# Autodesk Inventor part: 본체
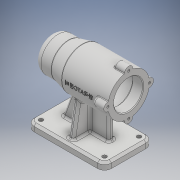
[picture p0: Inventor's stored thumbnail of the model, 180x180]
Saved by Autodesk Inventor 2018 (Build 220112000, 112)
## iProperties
Created: 2019-07
Part Number: 본체
Material: 일반
Document SubType Name: Modeling
Designer: USER
Density: 1 g/cm^3
Appearance: 기본값
Mass: 243.361 g
Surface Area: 663.658 cm^2
Volume: 243.361 cm^3
Author: USER
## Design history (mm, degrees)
sketch "스케치1"
  geometry: L1 (56, -35)-(-56, -35); L2 (-56, -35)-(-56, 35); L3 (-56, 35)-(56, 35); L4 (56, 35)-(56, -35); L5 (56, -35)-(-56, 35); L6 (-56, -35)-(56, 35); 1 further point
  constraints: 12 end point, 2 midpoint, 2 parallel, 1 horizontal, 1 perpendicular
  dimensions: "d0" = 112 distance of L2.end L3.end; "d1" = 70 distance of L1.end L2.end
extrude "돌출1" new body sketch "스케치1" distance "d2" = 10; taper "d3" = 0 deg
sketch "스케치2"
  geometry: L1 (56, 80)-(-56, 80); L2 (-56, 0)-(-56, 10) reference; L3 (56, 0)-(56, 10) reference; L4 (-56, 0)-(56, 0) reference; L5 (-56, 110)-(11, 110); L6 (11, 110)-(31, 105); L7 (31, 105)-(56, 105); L8 (56, 105)-(56, 80); L9 (-56, 80)-(-56, 110); 3 further points
  constraints: 12 end point, 2 midpoint, 2 vertical alignment, 1 horizontal, 1 parallel, 1 perpendicular, 1 vertical
  dimensions: "d4" = 80 distance between parallel lines of L4 L1; "d5" = 60 diameter of L5 L1; "d6" = 50 diameter of L7 L1; "d7" = 25 distance of L6.end L7.end; "d8" = 45 horizontal distance of L7.end L5.end
revolve "회전1" sketch "스케치2" stored, may be unused: angle "d9" = 90 deg
sketch "스케치3"
  geometry: L1 (56, 55)-(56, 105) reference; L2 (56, 80)-(-56, 80); L3 (-56, 50)-(-56, 110) reference; L4 (-56, 101)-(-41, 101); L5 (-41, 101)-(-41, 104); L6 (-41, 104)-(13, 104); L7 (13, 104)-(13, 101); L8 (13, 101)-(25, 101); L9 (25, 101)-(25, 97.5); L10 (25, 97.5)-(43, 97.5); L11 (43, 97.5)-(43, 96); L12 (43, 96)-(47, 96); L13 (47, 96)-(47, 90.5); L14 (47, 90.5)-(50, 90.5); L15 (50, 90.5)-(50, 80); 1 further point
  constraints: 26 end point, 10 perpendicular, 2 midpoint, 2 point on line, 1 horizontal, 1 vertical
  dimensions: "d10" = 42 diameter of L4 L2; "d11" = 48 diameter of L6 L2; "d12" = 42 diameter of L8 L2; "d13" = 54 distance of L5.end L6.end; "d14" = 15 distance of L4.start L4.end; "d15" = 12 distance of L7.end L8.end; "d16" = 18 distance of L9.end L10.end; "d17" = 35 diameter of L10 L2; "d18" = 32 diameter of L12 L2; "d19" = 4 distance of L11.end L12.end; "d20" = 3 distance of L13.end L14.end; "d21" = 21 diameter of L14 L2
revolve "회전2" sketch "스케치3" stored, may be unused: angle "d22" = 90 deg
sketch "스케치4"
  geometry: L1 (4, -28)-(-4, -28); L2 (-4, -28)-(-4, 28); L3 (-4, 28)-(4, 28); L4 (4, 28)-(4, -28); L5 (4, -28)-(-4, 28); L6 (-4, -28)-(4, 28); L7 (-56, 35)-(56, 35) reference; 1 further point
  constraints: 12 end point, 2 midpoint, 2 parallel, 1 horizontal, 1 perpendicular
  dimensions: "d23" = 8 distance of L2.end L3.end; "d25" = 7 distance between parallel lines of L7 L3
extrude "돌출2" join sketch "스케치4" stored distance "d26" = 10; taper "d27" = 0 deg
sketch "스케치5"
  geometry: L1 (-56, 10)-(56, 10) reference; L2 (36, 10)-(20.57, 52.393); L3 (11, 50)-(31, 55) reference; L4 (56, 0)-(56, 10) reference; 1 further point
  constraints: 2 end point, 2 point on line
  dimensions: "d28" = 110 deg angle of L1 L2; "d29" = 20 distance from line of L4 L2.start
feature "리브1" sketch "스케치5" dims "d30" = 1, "d31" = 8, "d32" = 0, "d33" = 0, "d34" = 1, "d35" = 1
sketch "스케치6"
  geometry: L1 (-56, 50)-(-4, 50) reference; L2 (-56, 0)-(-56, 10) reference; L3 (-56, 10)-(56, 10) reference; L4 (-31, 50)-(-31, 10); 1 further point
  constraints: 2 end point, 2 point on line, 1 perpendicular
  dimensions: "d37" = 25 distance between parallel lines of L2 L4
feature "리브2" sketch "스케치6" dims "d38" = 1, "d39" = 8, "d40" = 0, "d41" = 0, "d42" = 1, "d43" = 1
fillet "모깎기1" dims "d44" = 10
fillet "모깎기4" dims "d54" = 3
fillet "모깎기5" dims "d55" = 10
sketch "스케치8"
  geometry: C1 r 6 at (-30, 0); A1 r 30 centre (0, 0) between (29.314, -6.381) and (29.314, 6.381) reference; A2 r 30 centre (0, 0) between (29.732, 4) and (29.732, -4) reference; 1 further point
  constraints: 1 centre point, 1 horizontal alignment, 1 point on circle
  dimensions: "d56" = 12 diameter of C1
extrude "돌출3" join sketch "스케치8" distance "d57" = 16; taper "d58" = 0 deg
sketch "스케치9"
  geometry: A1 r 30 centre (30, 0) between (0.6, 5.97) and (0.6, -5.97) reference; A2 r 30 centre (30, 0) between (0.6, -5.97) and (24.03, -29.4) reference; A3 r 6 centre (0, 0) between (0.6, 5.97) and (0.6, -5.97) reference; 2 further points
  constraints: 1 coincident
hole "구멍2" sketch "스케치9" at (0, 0) diameter "d62" = 3.242; stored, may be unused: countersink angle "d66" = 90 deg, drill point angle "d68" = 118 deg; dims "d63" = 8, "d64" = 4, "d65" = 2, "d67" = 11
fillet "모깎기6" dims "d72" = 3
fillet "모깎기7" dims "d73" = 1
chamfer "모따기1" distance "d74" = 1; stored, may be unused: second distance "d75" = 2, angle "d76" = 45 deg
fillet "모깎기8" dims "d77" = 0.3
fillet "모깎기9" dims "d78" = 3
fillet "모깎기10" dims "d79" = 3
chamfer "모따기2" distance "d84" = 3; stored, may be unused: second distance "d85" = 2, angle "d86" = 45 deg
sketch "스케치13"
  geometry: A1 r 10 centre (-46, 25) between (-46, 35) and (-56, 25) reference; A2 r 10 centre (46, 25) between (56, 25) and (46, 35) reference; A3 r 10 centre (46, -25) between (46, -35) and (56, -25) reference; A4 r 10 centre (-46, -25) between (-56, -25) and (-46, -35) reference; 5 further points
  constraints: 4 coincident
hole "구멍3" sketch "스케치13" at (-46, 25), (46, 25), (46, -25), (-46, -25) diameter "d89" = 6; stored, may be unused: countersink angle "d93" = 90 deg, drill point angle "d95" = 118 deg; dims "d90" = 6, "d91" = 4, "d92" = 2, "d94" = 8
sketch "스케치14"
  geometry: 1 further point
sketch "스케치15"
  geometry: L1 (-28, 0)-(-28, 10) reference; L2 (-28, 10)-(-19.654, 57.334); L3 (4, 10)-(28, 10) reference; L4 (19.654, 57.334)-(28, 10); L5 (-32, 10)-(-25, 10) reference; L6 (25, 10)-(32, 10) reference; L7 (28, 10)-(28, 69.23) reference; L8 (-28, 10)-(-28, 69.23) reference; A1 r 30 centre (0, 80) between (4, 50.268) and (28, 69.23) reference; A2 r 30 centre (0, 80) between (-28, 69.23) and (-4, 50.268) reference; 1 further point
  constraints: 4 end point, 2 point on circle
  dimensions: "d96" = 100 deg angle of L5 L2; "d97" = 100 deg angle of L6 L4
extrude "돌출4" cut sketch "스케치15" stored distance "d98" = 10; taper "d99" = 0 deg
fillet "모깎기13" dims "d100" = 3
fillet "모깎기14" dims "d101" = 3
node "작업 평면5"
sketch "스케치16"
  geometry: L1 (-33.5, 6.771)-(-33.5, 29.226) reference; L2 (-16.5, 30)-(33.131, 30) reference; 2 further points
  constraints: 1 other
  dimensions: "d102" = 42 distance from line of L1 point (8.5, 0); "d103" = 30 distance from line of point (8.5, 0) L2
feature "엠보싱2" sketch "스케치16" dims "d0" = 112, "d1" = 70, "d104" = 0.5, "d105" = 0
node "솔리드1"
pattern_circular "원형 패턴1" dims angle "d60" = 360 deg
pattern_circular "원형 패턴2" dims angle "d70" = 360 deg
